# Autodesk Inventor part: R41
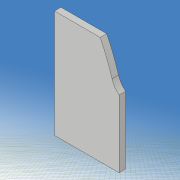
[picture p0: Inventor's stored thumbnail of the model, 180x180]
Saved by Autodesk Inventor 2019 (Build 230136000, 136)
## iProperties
Created: 2021-05
Part Number: R41
Material: 一般
Document SubType Name: Modeling
Designer: kikut
Density: 1 g/cm^3
Appearance: 既定
Mass: 0.0213701 g
Surface Area: 0.855673 cm^2
Volume: 0.0213701 cm^3
Author: kikut
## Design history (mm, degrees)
sketch "スケッチ1"
  geometry: L1 (80, 60)-(-80, 60); L2 (-80, 60)-(-80, -60); L3 (-80, -60)-(80, -60); L4 (80, -60)-(80, 60); L5 (80, 60)-(-80, -60); L6 (-80, 60)-(80, -60); 1 further point
  constraints: 12 end point, 2 midpoint, 2 parallel, 1 horizontal, 1 perpendicular
  dimensions: "d0" = 160 distance of L2.end L3.end; "d1" = 120 distance of L1.end L2.end
extrude "押し出し1" new body sketch "スケッチ1" stored distance "d2" = 0.6; taper "d3" = 0 deg
sketch "スケッチ2"
  geometry: L1 (-140, 0)-(140, 0) reference; L2 (0, -54)-(20, -30); L3 (0, 54)-(20, 30); L4 (0, -3)-(6.514, -3); L5 (6.514, -3)-(16, -6); L6 (16, -6)-(24, -3); L7 (24, -3)-(33.716, -3); L8 (0, 3)-(6.514, 3); L9 (6.514, 3)-(16, 6); L10 (16, 6)-(24, 3); L11 (24, 3)-(33.716, 3); L12 (0, -98)-(0, 98) reference; L13 (-100, -70)-(100, -70); L14 (100, -70)-(100, 70); L15 (100, 70)-(-100, 70); L16 (-100, 70)-(-100, -70); L17 (-100, -70)-(100, 70); L18 (100, -70)-(-100, 70); A1 r 60 centre (54.312, 28.5) between (0, 54) and (0, 3); A2 r 60 centre (54.312, -28.5) between (0, -3) and (0, -54); A3 r 18.111 centre (18, -12) between (20, -30) and (33.716, -3); A4 r 18.111 centre (18, 12) between (33.716, 3) and (20, 30); 1 further point
  constraints: 32 end point, 8 point on circle, 8 symmetric about line, 4 centre point, 3 horizontal, 2 collinear, 2 midpoint, 2 parallel, 1 perpendicular
  dimensions: "d5" = 60 radius of A1; "d6" = 6 distance of L8.start L4.start; "d7" = 108 distance of L3.start L2.start; "d8" = 0 horizontal distance of L3.start L8.start; "d9" = 60 distance of L3.end L2.end; "d10" = 0 horizontal distance of point (0, 0) L3.start; "d11" = 20 horizontal distance of L3.start L3.end; "d12" = 24 distance of A4.centre A3.centre; "d13" = 6 distance of L11.end L7.end; "d14" = 12 distance of L9.end L5.end; "d15" = 16 distance from line of L12 L5.end; "d16" = 24 distance from line of L6.end L12; "d17" = 200 distance of L14.end L15.end; "d18" = 140 distance of L15.end L13.start; "d30" = 18 distance from line of L12 A4.centre
extrude "押し出し2" cut sketch "スケッチ2" stored distance "d19" = 10; taper "d20" = 0 deg
sketch "スケッチ3"
  geometry: L1 (49.705, -17.97)-(33.948, -15.191); L2 (33.948, -15.191)-(34.295, -13.222); L3 (34.295, -13.222)-(50.052, -16); L4 (50.052, -16)-(49.705, -17.97); L5 (49.705, -17.97)-(34.295, -13.222); L6 (33.948, -15.191)-(50.052, -16); L7 (50.052, 16)-(34.295, 13.222); L8 (34.295, 13.222)-(33.948, 15.191); L9 (33.948, 15.191)-(49.705, 17.97); L10 (49.705, 17.97)-(50.052, 16); L11 (50.052, 16)-(33.948, 15.191); L12 (34.295, 13.222)-(49.705, 17.97); L13 (-112, 0)-(112, 0) reference; L14 (0, -84)-(0, 84) reference; 3 further points
  constraints: 24 end point, 4 midpoint, 4 parallel, 2 perpendicular, 2 symmetric about line
  dimensions: "d21" = 2 distance of L3.end L1.start; "d22" = 2 distance of L9.end L7.start; "d23" = 16 distance of L8.end L9.end; "d24" = 42 distance from line of L14 point (42, 15.596); "d26" = 10 deg angle of L7 L13; "d62" = 16 distance from line of L3.end L13
extrude "押し出し3" join sketch "スケッチ3" distance "d27" = 0.6; taper "d28" = 0 deg
fillet "フィレット1" dims "d31" = 2
fillet "フィレット2" dims "d32" = 1
sketch "スケッチ6"
  geometry: L1 (-20, 60)-(80, 60); L2 (80, 60)-(80, -60); L3 (80, -60)-(-20, -60); L4 (-20, -60)-(-20, 60); L5 (-46.168, 0)-(93.832, 0) reference; L6 (0, -84)-(0, 84) reference; L7 (30, 10)-(36, 10); L8 (36, 10)-(36, 20); L9 (36, 20)-(30, 20); L10 (30, 20)-(30, 10); 1 further point
  constraints: 16 end point, 4 parallel, 2 horizontal, 2 perpendicular, 1 other
  dimensions: "d63" = 120 distance of L3.end L1.start; "d64" = 100 distance of L1.start L1.end; "d65" = 20 distance between parallel lines of L6 L4; "d66" = 6 distance of L8.end L9.end; "d73" = 10 distance of L9.end L7.start; "d74" = 10 distance between parallel lines of L7 L5; "d75" = 50 distance between parallel lines of L10 L4
extrude "押し出し4" cut sketch "スケッチ6" stored distance "d70" = 10; taper "d71" = 0 deg
node "ソリッド1"
